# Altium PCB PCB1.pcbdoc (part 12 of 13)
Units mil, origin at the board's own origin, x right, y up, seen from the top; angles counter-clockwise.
Board outline 5895.51 x 5895.51 mil, 8 copper layers (Top Layer, L2_GND1, L3_SIG1, L4_GND2, L5_PWR, L6_SIG2, L7_GND3, Bottom Layer), stack 63.761 mil thick; 673 components, 558 nets, 2797 pads, 1861 vias.
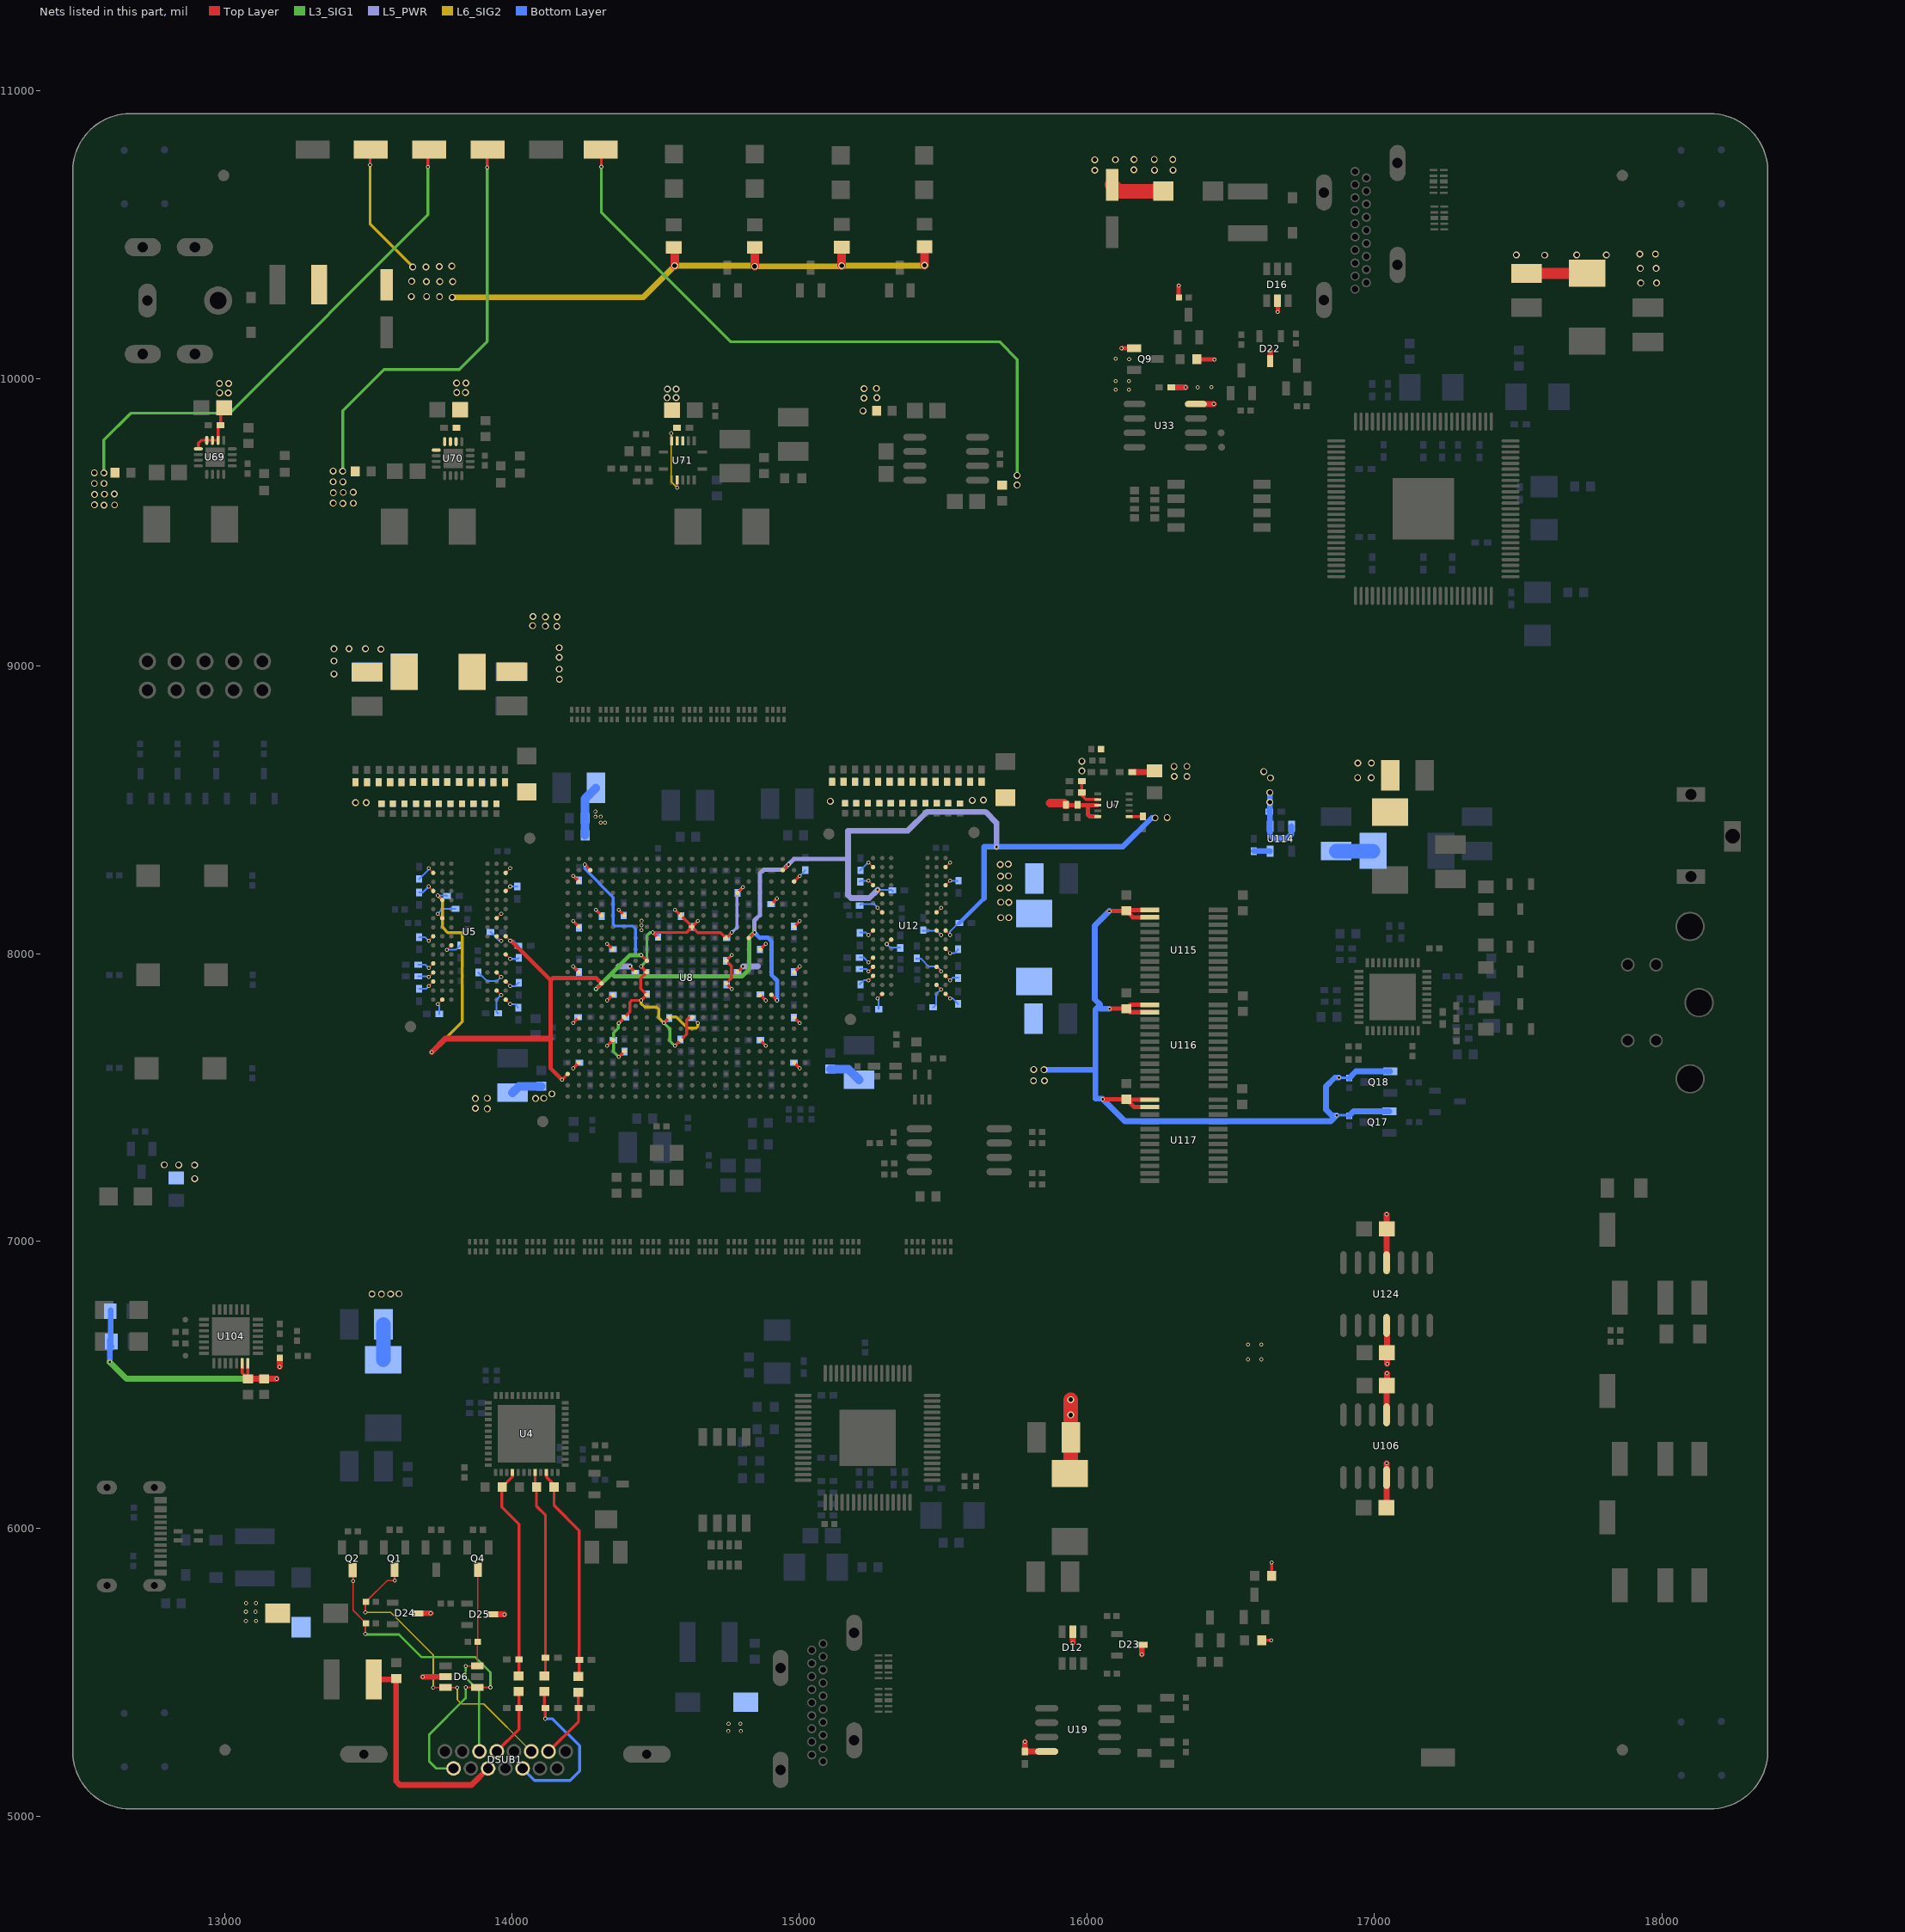
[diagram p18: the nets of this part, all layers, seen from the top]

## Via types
v1: diameter 23.62, hole 15.75, Top Layer to Bottom Layer, 621 vias
v2: diameter 13.8, hole 7.9, Top Layer to Bottom Layer, 567 vias
v3: diameter 13.78, hole 7.87, Top Layer to Bottom Layer, 529 vias
v4: diameter 13.78, hole 7.9, Top Layer to Bottom Layer, 114 vias
v5: diameter 15.75, hole 7.87, Top Layer to Bottom Layer, 16 vias
v6: diameter 24, hole 12, Top Layer to Bottom Layer, 10 vias
v7: diameter 11.81, hole 7.87, Top Layer to Bottom Layer, 4 vias

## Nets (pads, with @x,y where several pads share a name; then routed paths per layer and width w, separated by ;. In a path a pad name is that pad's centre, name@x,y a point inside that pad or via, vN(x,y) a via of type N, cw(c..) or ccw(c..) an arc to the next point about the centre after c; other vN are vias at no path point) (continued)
VCC_1V5: C42.2 C43.2 C44.2 C45.2 C46.2 C47.2 C48.2 C49.2 C50.2 C51.2 C52.2 C53.2 C66.2 C67.2 C68.2 C69.2 C70.2 C71.2 C72.2 C73.2 C74.2 C75.2 C76.2 C77.2 C120.2 C123.2 C311.2 C312.2 C345.1 C347.1 C349.1 L25.2 L34.1 Q17.1 Q18.1 R96.1 R180.2 R181.2 U7.2 U8.C2 U8.C21 U8.E19 U8.F4 U8.F6 U8.G2 U8.G21 U8.J5 U8.J18 U8.L2 U8.L7 U8.L16 U8.L21 U8.N5 U8.N18 U8.R2 U8.R21 U8.U5 U8.U18 U8.W2 U8.W21 U73.1 U115.1 U115.2 U116.1 U116.2 U117.1 U117.2 | length 6171.7
  Top Layer w10: v3(13914.39,10733.88) 13914.39,10800.96 U73.1@13915.39,10801.96 ; v2(14213.67,7601.05) U8.W2@14233.34,7620.73 ; v2(14213.67,7758.52) U8.R2@14233.34,7778.2 ; v2(14213.67,7955.37) U8.L2@14233.34,7935.7 ; v2(14213.67,8112.84) U8.G2@14233.34,8093.16 ; v2(14213.67,8270.32) U8.C2@14233.34,8250.65 ; v2(14292.41,8152.21) U8.F4@14312.08,8132.53 ; v2(14331.79,7679.79) U8.U5@14351.46,7699.47 ; v2(14331.79,7837.27) U8.N5@14351.46,7856.94 ; v2(14331.79,8034.1) U8.J5@14351.46,8014.43 ; v2(14371.15,8152.21) U8.F6@14390.82,8132.53 ; v2(14410.52,7955.37) U8.L7@14430.19,7935.7 ; U8.L16@14784.52,7935.7 v2(14804.2,7955.37) ; U8.U18@14863.26,7699.47 v2(14882.94,7679.79) ; U8.N18@14863.26,7856.94 v2(14882.94,7837.27) ; U8.J18@14863.26,8014.43 v2(14882.94,8034.1) ; U8.E19@14902.63,8171.9 v2(14922.31,8191.57) ; U8.W21@14981.36,7620.73 v2(15001.04,7601.05) ; U8.R21@14981.36,7778.2 v2(15001.04,7758.52) ; U8.L21@14981.36,7935.7 v2(15001.04,7955.37) ; U8.G21@14981.36,8093.16 v2(15001.04,8112.84) ; U8.C21@14981.36,8250.65 v2(15001.04,8270.32) ; C120.2@15981.86,8599.95 C123.2@15981.86,8559.95 15981.86,8550.5 15996.66,8535.7 U7.2@16037.24,8535.7
  Top Layer w15: v3(16055.36,7493.44) C347.1@16137.36,7493.44 C347.1@16139.06,7491.74 ; v3(16078.36,8148) 16078.8,8148.44 C345.1@16137.36,8148.44 ; v3(16079.36,7808) 16079.8,7808.44 C349.1@16137.36,7808.44 ; U117.2@16218.36,7466.15 16164.65,7466.15 C347.1@16139.06,7491.74 ; U117.1@16218.36,7491.74 C347.1@16139.06,7491.74 ; U116.2@16218.36,7796.15 16149.65,7796.15 C349.1@16137.36,7808.44 ; U116.1@16218.36,7821.74 16150.66,7821.74 C349.1@16137.36,7808.44 ; U115.2@16218.36,8126.15 16159.65,8126.15 C345.1@16137.36,8148.44 ; U115.1@16218.36,8151.74 16140.66,8151.74 C345.1@16137.36,8148.44
  L3_SIG1 w10: v1(13411.57,9677.79) 13411.57,9888.31 13554.67,10031.42 13816.93,10031.42 13914.43,10128.92 v3@13914.43,10733.84
  L5_PWR w20: 14370.36,7955.37 v2(14410.52,7955.37) ; v2(14804.2,7955.37) 14855.99,7955.37 14856.36,7955
  Bottom Layer w6: v2(14213.67,7601.05) 14233.49,7620.88 C52.2@14234.69,7620.88 ; v2(14213.67,7758.52) 14230.9,7775.75 C47.2@14230.9,7779 ; v2(14213.67,8112.84) 14233.36,8093.15 C51.2@14233.36,8089.54 ; v2(14213.67,8270.32) 14217.58,8270.32 C48.2@14233.36,8254.54 ; v2(14331.79,7679.79) 14334.61,7679.79 C44.2@14352.82,7698 ; v2(14331.79,7837.27) 14350.9,7856.38 C50.2@14350.9,7857 ; v2(14331.79,8034.1) 14332.8,8034.1 C45.2@14351.9,8015 ; v2(14371.15,8152.21) 14371.15,8150.75 C311.2@14389.36,8132.54 ; v2(14410.52,7955.37) 14428.81,7937.08 C49.2@14428.81,7932.42 ; C72.2@14784.9,7936 v2@14804.2,7955.3 ; C76.2@14862.36,8014.46 14863.3,8014.46 v2(14882.94,8034.1) ; C70.2@14863.82,7858 14882.94,7838.88 v2(14882.94,7837.27) ; C77.2@14864.82,7697 14865.73,7697 v2(14882.94,7679.79) ; C75.2@14901.9,8170 14922.31,8190.41 v2(14922.31,8191.57) ; C68.2@14979.36,7779.54 14980.02,7779.54 v2(15001.04,7758.52) ; C71.2@14980.9,7620 14982.09,7620 v2(15001.04,7601.05) ; C73.2@14981.36,8094.46 14982.66,8094.46 v2(15001.04,8112.84) ; C69.2@14982.36,7933.46 15001.04,7952.14 v2(15001.04,7955.37) ; v2(15001.04,8270.32) 15020.36,8289.64 C74.2@15020.36,8290.54
  Bottom Layer w10: v2(14213.67,7955.37) 14233.13,7935.91 C53.2@14233.25,7935.91 ; v2(14292.41,8152.21) 14312.36,8132.26 C46.2@14312.36,8130.54 ; v3(16868.82,7437.63) 16869.21,7438.02 R180.2@16914.09,7438.02 ; v3(16876.59,7568.85) 16877.46,7567.98 R181.2@16912.15,7567.98
  Bottom Layer w20: v1(15850.36,7596) 16027.61,7596 16029.36,7597.75 ; v3(16078.36,8148) 16027.36,8097 16027.36,7841 16046.36,7822 ; v3(16079.36,7808) 16046.36,7808 16046.36,7822 ; v3(16876.59,7568.85) 16862.21,7568.85 16831.36,7538 16831.36,7457 16850.73,7437.63 v3(16868.82,7437.63) 16848.19,7417 16131.8,7417 v3(16055.36,7493.44) 16052.8,7496 16029.36,7496 16029.36,7597.75 ; R180.2@16912.36,7436.04 16927.72,7451.4 Q17.1@17051.73,7451.4 ; R181.2@16912.36,7567.04 16935.72,7590.4 Q18.1@17054.73,7590.4 ; 16029.36,7597.75 16029.36,7805 16046.36,7822
  Bottom Layer w30: C42.2@14002.36,7516.26 14024.54,7538.44 C43.2@14102.36,7538.44 ; C67.2@15107.36,7598.44 15170.18,7598.44 C66.2@15207.36,7561.26
  other v1: 13914.36,7460 13873.36,7462 13873.36,7496 14082.36,7496 13914.36,7497 14111.36,7497 14139.36,7512 15814.36,7558 15852.36,7558 15815.36,7597 15982.36,8635 15982.36,8669 13378.63,9566.45 13412.15,9565.57 13448.58,9566.16 13378.92,9602.3 13413.31,9603.47 13448,9604.05 13378.34,9641.06 13412.15,9640.77 13378.34,9678.08
VCC_1V8: C337.2 C343.2 L42.1 U114.5 | length 184.9
  Bottom Layer w20: C343.2@16580.36,8356.54 16636.21,8356.54 U114.5@16636.82,8355.93
  Bottom Layer w50: C337.2@16867.36,8356.26 16994.51,8356.26 L42.1@16995.25,8357
VCC_3V3: C125.2 C150.2 C204.2 C208.2 C210.2 C211.2 C213.2 C215.2 C314.2 C315.2 C328.2 C344.2 L1.2 L23.2 L28.1 L29.1 L30.1 L31.1 L32.1 L39.1 Q9.1 R31.1 R164.2 R165.2 U19.8 U26.2 U27.2 U33.8 U72.1 U104.6 U104.7 U114.1 U114.3 | length 4143.4
  Top Layer w10: U104.6@13062.06,6575.31 13062.06,6542.1 C314.2@13081.75,6522.41 ; U104.7@13081.75,6575.31 C314.2@13081.75,6522.41 ; C314.2@13082.69,6521.47 C314.2@13081.75,6522.41 ; U72.1@13706.82,10808.85 13708.31,10807.35 v3(13708.31,10735.63) ; U26.2@16607.64,5611.71 v3(16641.36,5611.71) ; v3(16642.36,5883) 16642.64,5882.71 U27.2@16642.64,5836.71
  Top Layer w15: v3(16120.2,10105.05) Q9.1@16163.22,10105.05
  Top Layer w20: C314.2@13082.69,6521.47 13138.26,6521.47 C315.2@13138.36,6521.56 v3(13181.36,6521.56) ; v3(13192.36,6563) 13192.69,6563.33 R31.1@13192.69,6593.52 ; C150.2@15784.31,5221.87 C150.2@15787.85,5225.41 ; v3(15784.36,5259) 15784.36,5228.9 C150.2@15787.85,5225.41 ; U19.8@15860.16,5225.41 C150.2@15787.85,5225.41 ; C125.2@16156.82,8631 16231.32,8631 L1.2@16235.36,8635.04 ; C210.2@16293.82,9969 v3(16343.36,9969) ; U33.8@16378.86,9911 v3(16441.36,9911)
  Top Layer w40: C213.2@17528.83,10365.31 17739.56,10365.31 L31.1@17739.86,10365.61
  Top Layer w50: L30.1@15940.93,6191.88 15943.68,6194.62 C211.2@15943.68,6317.79 v1(15943.68,6395.66) 15943.68,6448.68 v1(15943.36,6449)
  L3_SIG1 w10: v1(12580.87,9671.84) 12580.87,9786.14 12674.08,9879.35 13018.85,9879.35 13708.31,10568.81 v3(13708.31,10735.63)
  L3_SIG1 w20: v3(12601.03,6580.15) 12659.62,6521.56 v3(13181.36,6521.56)
  Bottom Layer w20: v3(12601.03,6580.15) 12601.6,6580.72 R164.2@12601.6,6656.88 ; R165.2@12604.86,6759.82 12604.86,6635.81 R164.2@12606.91,6633.76 ; v1(16636.36,8560) v1(16636.36,8526.11) 16636.36,8496.46 C344.2@16633.9,8494 16636.83,8491.07 U114.1@16636.83,8442.55 16636.83,8412.53 16648.36,8401 16697.36,8401 16711.62,8415.26 U114.3@16711.62,8442.55
  Bottom Layer w50: L32.1@13552.55,6587.3 13553.1,6587.84 C215.2@13553.1,6711
  other v1: 13513.39,6815.89 13546.42,6815.6 13578.08,6816.06 13607.46,6816.97 16638.36,8611 16941.61,8612.22 16989.1,8611.89 16303.82,8616.44 16347.87,8616.44 16615.36,8633 16303.15,8650.97 16347.87,8651.19 16941.94,8662.7 16989.43,8662.7 13381.55,8972.51 13381.25,9017.58 13544.76,9058.99 13381.25,9059.6 13433.31,9059.9 13490.86,9059.9 12547.93,9560.5 12581.45,9559.62 12617.89,9560.21 12548.23,9596.35 12582.62,9597.51 12617.3,9598.1 12547.64,9635.11 12581.45,9634.82 12547.64,9672.13 17926.44,10331.81 17980.99,10331.81 17924.95,10382.61 17979.49,10382.61 17592.04,10428.77 17493.42,10429.77 17703.62,10429.77 17806.73,10429.77 17922.96,10432.42 17977.5,10432.42
  other v3: 16100.36,9961 16146.36,9961 16385.36,9969 16433.36,9970 16100.36,9991 16146.36,9991 16146.83,10067.36 16100.36,10069
VCC_5V: C153.1 C192.1 C193.2 C196.2 C199.2 C217.1 C218.1 C219.1 C354.2 C356.2 D5.2 D6.5 D11.2 D12.5 D16.5 D17.1 D22.3 D23.3 D24.3 D25.3 D29.1 F2.1 L44.1 R112.2 R143.2 R144.2 R145.2 R147.2 R148.2 U11.1 U31.2 U69.10 U69.11 U69.12 U69.13 U70.10 U70.11 U70.12 U70.13 U71.4 U71.5 U71.6 U71.10 U106.4 U124.4 | length 3801.1
  Top Layer w5: v3(14574.64,9620.19) 14574.79,9620.35 U71.10@14574.79,9650.03
  Top Layer w10: U69.13@12909.23,9755.26 12909.23,9774.88 12919.36,9785 12977.91,9785 U69.10@12978.12,9784.78 12978.12,9829.31 C217.1@12986.82,9838 12986.82,9886.09 C193.2@12998.73,9898 ; v3(13506.83,10742.48) 13506.83,10796.91 U11.1@13516.66,10806.75
  Top Layer w15: R112.2@16319.12,10280.07 16319.12,10322.35 v3(16319.57,10322.8) ; U31.2@16380.2,10066.16 16443.07,10066.16 v3(16443.29,10065.94) ; v3(16663.44,10231.78) 16663.67,10232 D16.5@16663.67,10271.85
  Top Layer w20: D24.3@13669.67,5705.83 v3(13717.47,5705.83) ; v3(13690.13,5485.15) 13690.42,5484.86 D6.5@13768.82,5484.86 ; D25.3@13932.29,5702.36 13973.09,5702.36 v3(13973.48,5701.98) ; v3(15950.92,5603) D12.5@15950.92,5641.45 ; v3(16190.67,5563) D23.3@16190.67,5596.33 ; v3(16637.42,10095.3) 16638.09,10094.64 D22.3@16638.09,10059.1 ; U106.4@17042.36,6396.02 17042.36,6496.63 C354.2@17043.73,6498 17043.73,6540.23 v3(17043.57,6540.4) ; U124.4@17042.36,6925.02 C356.2@17042.36,7042.63 ; v3(17042.4,7093.84) C356.2@17042.36,7042.63 ; C356.2@17042.73,7043 C356.2@17042.36,7042.63
  Top Layer w30: R143.2@14563.18,10455.6 14566.36,10452.42 v1(14566.36,10392) ; v1(14844.36,10390) R144.2@14844.36,10455.6 ; v1(15147.36,10392) R145.2@15147.36,10456.63 ; v1(15435.36,10394) R147.2@15435.36,10457.63
  Top Layer w50: C153.1@16087.36,10673.68 16110.04,10651 D17.1@16266.04,10651
  L6_SIG2 w5: v3(14554.1,9809.28) 14554.1,9640.74 v3(14574.64,9620.19)
  L6_SIG2 w10: v3(13506.83,10742.48) 13506.83,10536.53 v1(13655.36,10388)
  L6_SIG2 w20: v1(13792.36,10282) 14456.36,10282 v1(14566.36,10392) 14842.36,10392 v1(14844.36,10390) 15145.36,10390 v1(15147.36,10392) 15433.36,10392 v1(15435.36,10394)
  other v1: 12896.5,7217.37 12791.18,7265.3 12840.93,7265.18 12896.37,7264.79 15221.06,9887.45 15224.77,9931.95 14539.88,9932.69 14571.17,9933.39 15269.27,9933.11 12983.1,9950.17 13013.12,9949.88 13808.16,9951.15 13838.18,9950.86 14540.94,9962.92 14571.17,9962.92 15225,9964.86 15267.88,9965.32 12982.81,9982.81 13015.16,9982.81 13807.87,9983.79 13840.22,9983.79 13748.36,10284 13650.36,10285 13703.36,10285 13702.36,10337 13749.36,10337 13794.36,10337 13651.36,10338 13701.36,10388 13747.36,10389 13791.36,10391 16027.49,10724.21 16299.68,10724.46 16163.61,10725.29 16235.01,10724.63 16027.46,10760.49 16099.19,10760.82 16163.94,10761.16 16298.68,10761.32 16234.34,10761.82
  other v4: 14752.7,5295.96 14796.27,5295.96 14753.73,5321.58 14795.24,5321.58 13074.63,5679.2 13109.71,5678.97 13074.63,5711.32 13108.8,5711.54 13075.09,5741.16 13109.49,5741.38
VCC_AUX: C17.2 C18.2 C19.2 C20.2 C21.2 C22.2 C23.2 C24.2 C25.2 C29.2 C205.2 C303.2 C304.2 C305.2 C306.2 C307.2 C308.2 C309.2 L28.2 U8.D16 U8.F11 U8.G12 U8.H9 U8.H15 U8.K15 U8.L8 U8.M15 U8.N8 U8.R6 U8.R10 U8.R12 U8.U11 U8.V6 | length 2504.9
  Top Layer w10: v2(14371.15,7640.42) U8.V6@14390.82,7660.1 ; v2(14371.15,7758.52) U8.R6@14390.82,7778.2 14410.36,7797.73 14410.36,7831 14416.63,7837.27 v2(14449.89,7837.27) U8.N8@14469.56,7856.94 14448.36,7878.15 14448.36,7914.49 U8.L8@14469.56,7935.7 v2(14449.89,7955.37) ; U8.H9@14508.93,8053.8 v2(14489.26,8073.47) 14607.37,8073.47 U8.G12@14627.06,8093.16 ; v2(14528.63,7758.52) U8.R10@14548.3,7778.2 ; v2(14567.99,7679.79) U8.U11@14587.66,7699.47 14608.36,7720.16 14608.36,7769 14617.55,7778.2 U8.R12@14627.06,7778.2 ; v2(14567.99,8152.21) U8.F11@14587.66,8132.53 U8.G12@14627.03,8093.16 ; v2(14646.74,8112.84) U8.G12@14627.06,8093.16 ; v2(14764.84,7876.62) U8.M15@14745.16,7896.3 14763.36,7914.49 14763.36,7956.86 U8.K15@14745.16,7975.06 v2(14764.84,7994.73) ; v2(14764.84,8073.47) U8.H15@14745.16,8053.8 14725.96,8073 14647.23,8073 U8.G12@14627.06,8093.16 ; U8.D16@14784.52,8211.27 v2(14804.2,8230.95)
  L3_SIG1 w10: v2(14371.15,7640.42) 14353.36,7658.21 14353.36,7724 14370.36,7741 14370.36,7757.73 v2(14371.15,7758.52) ; v2(14449.89,7955.37) 14469.36,7974.84 14469.36,8062 14480.83,8073.47 v2(14489.26,8073.47) ; v2(14528.63,7758.52) 14549.36,7737.79 14549.36,7696 14565.57,7679.79 v2(14567.99,7679.79)
  L5_PWR w10: v2(14764.84,8073.47) 14779.37,8088 14782.36,8088 14782.36,8209.11 v2(14804.2,8230.95)
  L6_SIG2 w10: v2(14449.89,7837.27) 14449.89,7826.47 14462.36,7814 14503.36,7814 14510.36,7807 14510.36,7776.79 v2(14528.63,7758.52) 14550.11,7780 14571.36,7780 14610.36,7741 14641.36,7741 14646.74,7746.38 v2(14646.74,7758.52)
  Bottom Layer w6: v2(14371.15,7640.42) 14372.24,7640.42 C309.2@14391.36,7659.54 ; v2(14371.15,7758.52) 14375.34,7758.52 C22.2@14394.82,7778 ; v2(14449.89,7837.27) 14469.28,7856.67 C306.2@14469.28,7858.91 ; v2(14449.89,7955.37) 14467.36,7937.9 C305.2@14467.36,7934.54 ; v2(14528.63,7758.52) 14529.96,7758.52 C304.2@14547.73,7776.29 ; v2(14567.99,7679.79) 14586.36,7698.16 C25.2@14586.36,7701.46 ; v2(14567.99,8152.21) 14588.36,8131.84 C21.2@14588.36,8130.54 ; C20.2@14625.36,8093.54 14644.66,8112.84 v2(14646.74,8112.84) ; C19.2@14625.9,7776 14629.26,7776 v2(14646.74,7758.52) ; C307.2@14746.82,8054 14764.84,8072.02 v2(14764.84,8073.47) ; C24.2@14785.36,8210.54 14804.2,8229.38 v2(14804.2,8230.95)
  Bottom Layer w10: v2(14489.26,8073.47) 14497.43,8073.47 C303.2@14509.36,8061.54 ; C23.2@14743.02,7973.84 14743.94,7973.84 v2(14764.84,7994.73) ; C308.2@14746.91,7892.07 14749.39,7892.07 v2(14764.84,7876.62)
  Bottom Layer w30: C18.2@14254.92,8411 C29.2@14254.92,8471 14254.92,8538.82 C17.2@14292.1,8576
  other v1: 14165.36,8954 14164.36,8989 14164.36,9030 14164.36,9064
  other v4: 14451.36,8082 14451.36,8098 14451.36,8114 14308.54,8455.53 14324.17,8455.53 14290.36,8475.78 14308.54,8475.78 14290.36,8494
VDD_DDR3: C261.2 C262.2 C263.2 C264.2 C265.2 C266.2 C267.2 C268.2 C269.2 C270.2 C271.2 C272.2 C273.2 C274.2 C275.2 C276.2 C277.2 C278.2 C279.2 C280.2 C281.2 C282.2 C283.2 C284.2 C285.2 C286.2 C287.2 C288.2 C289.2 C290.2 C291.2 C292.2 C313.2 L34.2 U5.A1 U5.A8 U5.B2 U5.C1 U5.C9 U5.D2 U5.D9 U5.E9 U5.F1 U5.G7 U5.H2 U5.H9 U5.K2 U5.K8 U5.N1 U5.N9 U5.R1 U5.R9 U12.A1 U12.A8 U12.B2 U12.C1 U12.C9 U12.D2 U12.D9 U12.E9 U12.F1 U12.G7 U12.H2 U12.H9 U12.K2 U12.K8 U12.N1 U12.N9 U12.R1 U12.R9 | length 2304
  Top Layer w4.7: v2(13710.63,7887.02) U5.C9@13726.38,7902.77 ; v2(13710.63,7918.52) U5.D9@13726.38,7934.27 ; v2(13710.63,7950.02) U5.E9@13726.38,7965.76 ; v2(13710.63,8044.51) U5.H9@13726.38,8060.25 ; v2(13710.63,8233.48) U5.N9@13726.38,8217.73 ; v2(13710.63,8296.47) U5.R9@13726.38,8280.72 ; v2(13742.12,7824.03) U5.A8@13757.87,7839.78 ; v2(13742.12,8138.98) U5.K8@13757.87,8123.24 ; v2(13773.62,8013.02) U5.G7@13789.37,8028.76 ; U5.B2@13946.85,7871.28 v2(13962.59,7855.53) ; U5.D2@13946.85,7934.27 v2(13962.59,7918.52) ; U5.H2@13946.85,8060.25 v2(13962.59,8044.51) ; U5.K2@13946.85,8123.24 v2(13962.59,8138.98) ; U5.A1@13978.34,7839.78 v2(13994.08,7824.03) ; U5.C1@13978.34,7902.77 v2(13994.08,7887.02) ; U5.F1@13978.34,7997.26 v2(13994.08,7981.52) ; U5.N1@13978.34,8217.73 v2(13994.08,8233.48) ; U5.R1@13978.34,8280.72 v2(13994.08,8296.47) ; v2(15240.63,7907.02) U12.C9@15256.38,7922.77 ; v2(15240.63,7938.52) U12.D9@15256.38,7954.27 ; v2(15240.63,7970.02) U12.E9@15256.38,7985.76 ; v2(15240.63,8064.51) U12.H9@15256.38,8080.25 ; v2(15240.63,8253.48) U12.N9@15256.38,8237.73 ; v2(15240.63,8316.47) U12.R9@15256.38,8300.72 ; v2(15272.12,7844.03) U12.A8@15287.87,7859.78 ; v2(15272.12,8158.98) U12.K8@15287.87,8143.24 ; v2(15303.62,8033.02) U12.G7@15319.37,8048.76 ; U12.B2@15476.85,7891.28 v2(15492.59,7875.53) ; U12.D2@15476.85,7954.27 v2(15492.59,7938.52) ; U12.H2@15476.85,8080.25 v2(15492.59,8064.51) ; U12.K2@15476.85,8143.24 v2(15492.59,8158.98) ; U12.A1@15508.34,7859.78 v2(15524.08,7844.03) ; U12.C1@15508.34,7922.77 v2(15524.08,7907.02) ; U12.F1@15508.34,8017.26 v2(15524.08,8001.52) ; U12.N1@15508.34,8237.73 v2(15524.08,8253.48) ; U12.R1@15508.34,8300.72 v2(15524.08,8316.47)
  Bottom Layer w6: C275.2@13673.82,7921 13708.16,7921 v2(13710.63,7918.52) ; C265.2@13673.82,7961 13699.65,7961 v2(13710.63,7950.02) ; C274.2@13677.36,7877.46 13701.07,7877.46 v2(13710.63,7887.02) ; C266.2@13677.36,8057.46 13697.68,8057.46 v2(13710.63,8044.51) ; C267.2@13677.36,8212.46 13689.62,8212.46 v2(13710.63,8233.48) ; C268.2@13677.36,8259.54 13710.63,8292.82 v2(13710.63,8296.47) ; v2(13742.12,7824.03) 13746.82,7819.34 C273.2@13746.82,7790 ; v2(13742.12,8138.98) 13759.3,8156.16 C276.2@13804.64,8156.16 ; v2(13773.62,8013.02) 13805.2,8013.02 C269.2@13820.98,8028.8 ; C272.2@13883.14,7934.47 13912.61,7905 13949.07,7905 v2(13962.59,7918.52) ; C264.2@13926.05,8075.32 13956.86,8044.51 v2(13962.59,8044.51) ; C263.2@13952.26,7792.35 13946.36,7798.25 13946.36,7840 13961.89,7855.53 v2(13962.59,7855.53) ; v2(13994.08,7824.03) 14010.78,7824.03 C271.2@14022.36,7812.46 ; v2(13994.08,7887.02) 14011.77,7887.02 C262.2@14023.62,7898.87 ; v2(13994.08,7981.52) 14020.17,7981.52 C270.2@14024.57,7985.92 ; v2(13994.08,8233.48) C261.2@14019.36,8233.46 ; C279.2@15209.43,7986.82 15223.83,7986.82 v2(15240.63,7970.02) ; C288.2@15209.57,7892.73 15223.86,7907.02 v2(15240.63,7907.02) ; C277.2@15210.3,8250.64 15213.13,8253.48 v2(15240.63,8253.48) ; C281.2@15210.46,8168.55 15214.26,8172.35 15258.91,8172.35 15272.12,8159.13 v2(15272.12,8158.98) ; C285.2@15211.14,8289.4 15238.21,8316.47 v2(15240.63,8316.47) ; C278.2@15211.36,8073.29 15231.85,8073.29 v2(15240.63,8064.51) ; C287.2@15211.67,7945.95 15233.2,7945.95 v2(15240.63,7938.52) ; v2(15272.12,7844.03) 15274.87,7841.29 C280.2@15274.87,7806.65 ; v2(15303.62,8033.02) 15316.01,8020.63 C286.2@15350.24,8020.63 ; C283.2@15405.69,7981.68 15423.6,7981.68 15450.14,7955.13 15478.57,7955.13 15492.59,7941.12 v2(15492.59,7938.52) ; C282.2@15428.34,8079.99 15477.1,8079.99 v2(15492.59,8064.51) ; C289.2@15465.82,7813 15475.36,7822.54 15475.36,7858.3 v2(15492.59,7875.53) ; v2(15524.08,7844.03) 15532.59,7844.03 C290.2@15551.25,7825.38 ; v2(15524.08,7907.02) 15533.22,7916.17 C291.2@15552.72,7916.17 ; v2(15524.08,8001.52) 15539.28,8001.52 C292.2@15552.51,8014.75 ; v2(15524.08,8253.48) 15549.54,8253.48 C284.2@15550.93,8252.09
  other v1: 15700.36,8125 15728.36,8125 15728.36,8178 15700.36,8179 15698.36,8228 15728.36,8229 15699.36,8269 15727.36,8270 15698.36,8310 15726.36,8311 14156.36,9138 14116.36,9139 14072.36,9140 14116.36,9171 14157.36,9171 14073.36,9172
VDD_DDR3_REF: C102.1 C103.1 C104.1 C105.1 C124.1 U5.H1 U5.M8 U7.6 U8.B3 U8.B20 U8.H17 U8.K8 U8.M4 U8.N19 U8.Y1 U12.H1 U12.M8 | length 6372
  Top Layer w4.7: v2(13742.12,8201.99) U5.M8@13757.87,8186.24 ; U5.H1@13978.34,8060.25 v2(13994.08,8044.51) ; v2(15272.12,8221.99) U12.M8@15287.87,8206.24 ; U12.H1@15508.34,8080.25 v2(15524.08,8064.51)
  Top Layer w10: v2(14174.29,7561.68) U8.Y1@14193.96,7581.35 ; v2(14253.04,8309.69) U8.B3@14272.71,8290.01 ; v2(14292.41,7876.62) U8.M4@14312.08,7896.3 ; v2(14449.89,7994.73) U8.K8@14469.56,7975.06 ; U8.H17@14823.89,8053.8 v2(14843.57,8073.47) ; U8.N19@14902.63,7856.94 v2(14922.31,7837.27) ; U8.B20@14942,8290.01 v2(14961.68,8309.69) ; U7.6@16147.47,8476.6 16193.5,8476.6 C124.1@16194.36,8477.46
  Top Layer w15: v2(13994.08,8044.51) 13997.85,8044.51 14135.36,7907 ; v2(14174.29,7561.68) 14135.36,7600.61 14135.36,7703.68 14135.36,7907 ; U8.M4@14312.08,7896.3 14292.81,7915.57 14143.93,7915.57 14135.36,7907
  Top Layer w20: v3(13721.36,7657) 13768.36,7704 14135.03,7704 14135.36,7703.68
  L3_SIG1 w15: v2(14292.41,7876.62) 14346.74,7930.95 ; v2(14449.89,7994.73) 14410.52,7994.73 14346.74,7930.95 ; v2(14843.57,8073.47) 14825.36,8055.26 14825.36,7946 14800.36,7921 14356.69,7921 14346.74,7930.95
  L5_PWR w15: v2(14843.57,8073.47) 14843.57,8115.21 14862.15,8133.79 14862.15,8277.09 14876.15,8291.09 14943.08,8291.09 v2(14961.68,8309.69) 14981.13,8329.15 15169.36,8329.15
  L5_PWR w20: v2(15272.12,8221.99) 15243.14,8193 15179.36,8193 15169.36,8203 15169.36,8329.15 15169.36,8427.25 15377.57,8427.25 15443.44,8493.11 15647.25,8493.11 15685.36,8455 v4(15685.36,8371)
  L6_SIG2 w10: v3(13721.36,7657) 13827.36,7763 13827.36,8073 13777.36,8073 13758.22,8092.14 13758.22,8186 13758.11,8186 v2(13742.12,8201.99)
  Bottom Layer w6: v2(13742.12,8201.99) 13772.09,8201.99 C102.1@13774.04,8200.03 ; v2(13994.08,8044.51) 14005.48,8044.51 C103.1@14022.42,8027.56 ; v2(15272.12,8221.99) 15319.81,8221.99 C104.1@15326.8,8214.99 ; v2(15524.08,8064.51) 15524.08,8076.84 C105.1@15554.09,8106.85
  Bottom Layer w10: v2(14253.04,8309.69) 14253.04,8295.32 14352.36,8196 14352.36,8102 14358.36,8096 14420.16,8096 14430.16,8086 14430.16,8001.45 14436.88,7994.73 v2(14449.89,7994.73)
  Bottom Layer w15: v2(14843.57,8073.47) 14862.04,8055 14891.36,8055 14902.53,8043.83 14902.53,7925.83 14922.31,7906.05 v2(14922.31,7837.27) ; C105.1@15555.9,8106 15642.36,8192.46
  Bottom Layer w20: 15642.36,8192.46 15642.36,8372 16125.36,8372 16225.36,8472 v1(16237.36,8472)
  other v1: 16279.36,8473
VEE_N5V: C355.2 C357.2 L45.2 U106.11 U124.11 U126.1 | length 2581.8
  Top Layer w10: U126.1@14309.08,10806.94 14311.07,10804.95 v3(14311.07,10735.88)
  Top Layer w20: C355.2@17041.73,6073 17042.36,6073.63 U106.11@17042.36,6177.98 v3(17042.36,6228) ; U124.11@17042.36,6706.98 17043.73,6705.61 C357.2@17043.73,6612 17043.73,6573.63 v3(17044.36,6573)
  L3_SIG1 w10: v3(14311.07,10735.88) 14311.27,10735.68 14311.27,10576.45 14760.13,10127.59 15695.68,10127.59 15757.31,10065.95 v1(15757.31,9663.11)
  other v1: 15757.12,9629.3
  other v3: 16560.36,6589 16606.36,6589 16606.36,6640 16560.36,6641
VGA_5V: C118.2 DSUB1.9 U18.2 | length 789.7
  Top Layer w20: U18.2@13519.33,5476 13594.92,5476 C118.2@13598.36,5479.44 C118.2@13602.36,5483.44 ; C118.2@13597.36,5476.44 13597.36,5122 13610.36,5109 13859.82,5109 DSUB1.9@13917.3,5166.47
VGA_B: C114.2 R84.2 U4.28 U17.1 | length 748.1
  Top Layer w10: U4.28@14002.15,6196.14 14002.15,6181.13 R84.2@13966.02,6145 13965.36,6144.34 13965.36,6075 14024.82,6015.54 C114.2@14024.82,5546 14024.82,5490.02 U17.1@14023.36,5488.56
VGA_G: C113.2 R85.2 U4.32 U16.1 | length 724.5
  Top Layer w10: U4.32@14080.89,6196.14 14080.89,6150.13 R85.2@14086.02,6145 14085.36,6144.34 14085.36,6079 14116.9,6047.46 C113.2@14116.9,5551 14116.9,5492.1 U16.1@14113.36,5488.56
VGA_R: C112.2 R86.2 U4.34 U15.1 | length 758.6
  Top Layer w10: U4.34@14120.26,6196.14 14120.26,6179.33 14146.7,6152.89 R86.2@14146.7,6145 14146.7,6080.66 14234.21,5993.14 C112.2@14234.21,5543.68 14234.21,5489.78 U15.1@14230.67,5486.24
VGA_SCL: D6.1 DSUB1.15 Q2.3 R91.1 | length 1276.2
  Top Layer w4.7: Q2.3@13446.36,5855.98 13447.36,5854.98 v3(13447.36,5818) 13447.36,5716.35 R91.1@13492.48,5671.23 13490.36,5669.1 v3(13490.36,5634) ; v3(13839.35,5448.37) 13839.53,5448.19 D6.1@13879.85,5448.19 v3(13925.36,5448.19)
  L3_SIG1 w7.9: v3(13490.36,5634) 13492.36,5632 13607.36,5632 13685.36,5554 13871.36,5554 13925.36,5500 v3(13925.36,5448.19) ; DSUB1.15@13797.22,5166.47 13736.88,5166.47 13712.36,5191 13712.36,5284 13839.36,5411 v3(13839.35,5448.37)
  Bottom Layer w4.7: v3(13925.36,5448.19) v3@13925.36,5449
VGA_SDA: D6.6 DSUB1.12 Q1.3 R90.2 | length 1074.6
  Top Layer w4.7: v3(13490.36,5709) 13490.36,5744.1 R90.2@13492.48,5746.23 13566.25,5820 v3(13592.36,5820) 13592.05,5820.31 Q1.3@13592.05,5856.67 ; v3(13726.36,5447) 13726.62,5447.26 D6.6@13770.54,5447.26 ; D6.6@13769.61,5448.19 D6.6@13770.54,5447.26 ; v3(13809.47,5447.26) D6.6@13770.54,5447.26
  L6_SIG2 w5: v3(13490.36,5709) 13578.36,5709 13726.36,5561 v3(13726.36,5447) ; v3(13809.47,5447.26) 13810.36,5446.37 13810.36,5406 13825.36,5391 13901.94,5391 DSUB1.12@14067.41,5225.53
VGAC_B: C115.2 DSUB1.3 U17.2 | length 240.6
  Top Layer w10: DSUB1.3@13947.33,5225.53 14024.82,5303.01 C115.2@14024.82,5376 14024.82,5431.98 U17.2@14023.36,5433.44
VGAC_G: C116.2 DSUB1.2 U16.2 | length 570.5
  Top Layer w10: U16.2@14113.36,5433.44 14113.36,5379.54 C116.2@14116.9,5376 14116.36,5375.46 v3(14116.36,5339)
  Bottom Layer w10: DSUB1.2@14037.37,5166.47 14078.85,5125 14203.36,5125 14235.36,5157 14235.36,5245 14141.36,5339 v3(14116.36,5339)
VGAC_R: C117.2 DSUB1.1 U15.2 | length 249.4
  Top Layer w10: DSUB1.1@14127.45,5225.53 14231.9,5329.97 C117.2@14231.9,5376 14230.67,5377.22 U15.2@14230.67,5431.13
VSYC: D6.3 DSUB1.14 Q4.3 R95.1 | length 692.2
  Top Layer w4.7: v3(13839.13,5522.09) 13878.95,5522.09 D6.3@13879.85,5522.99 13879.85,5605.6 R95.1@13881.42,5607.17 13881.42,5856.04 Q4.3@13882.05,5856.67
  L3_SIG1 w7.9: v3(13839.13,5522.09) 13839.13,5483.22 13885.36,5437 13885.36,5227.47 DSUB1.14@13887.29,5225.53
VTT_DDR3: C78.2 C79.2 C80.2 C81.2 C82.2 C83.2 C84.2 C85.2 C86.2 C87.2 C88.2 C89.2 C90.2 C91.2 C92.2 C93.2 C94.2 C95.2 C96.2 C97.2 C98.2 C99.2 C100.2 C101.2 C121.2 C122.2 C220.2 C221.2 C222.2 C223.2 C224.2 C225.2 C226.2 C227.2 C228.2 C229.2 C230.2 C231.2 C232.2 C233.2 C234.2 C235.2 C236.2 C237.2 C238.2 C239.2 C240.2 C241.2 C242.2 C243.2 C244.2 C245.2 C246.2 C247.2 C248.2 C249.2 C250.2 C251.2 C259.1 C260.1 R27.2 R29.2 R30.2 R32.2 R33.2 R34.2 R35.2 R36.2 R37.2 R38.2 R39.2 R40.2 R41.2 R42.2 R43.2 R44.2 R45.2 R46.2 R47.2 R48.2 R49.2 R50.2 R54.2 R56.2 R57.2 R59.2 R60.2 R61.2 R62.2 R63.2 R64.2 R65.2 R66.2 R67.2 R68.2 R69.2 R70.2 R71.2 R72.2 R73.2 R74.2 R75.2 R76.2 R77.2 U7.3 U7.5 | length 237.3
  Top Layer w15: C122.2@15927.36,8517.46 15928.82,8516 U7.3@16037.24,8516 ; 16003.36,8515.99 16003.36,8483 16009.76,8476.6 U7.5@16037.24,8476.6
  Top Layer w30: 15872.36,8523 15921.82,8523 C122.2@15927.36,8517.46
  other v1: 13456.36,8525 13493.36,8525 15107.36,8530 15601.36,8533 15640.36,8534
pads on no net: CN2.7 CN2.8 D12.3 D16.3 DSUB1.4 DSUB1.11 R78.1 RN13.1 RN13.8 RN21.1 RN21.8 RN22.1 RN22.2 RN22.7 RN22.8 U2.2 U2.7 U2.49 U2.50 U2.51 U2.52 U2.53 U2.54 U2.55 U2.56 U2.59 U2.60 U2.61 U2.62 U2.63 U2.64 U2.65 U2.66 U2.69 U2.70 U2.71 U2.72 U2.73 U2.74 U2.75 U2.77 U2.96 U3.49 U5.J1 U5.J9 U5.L1 U5.L9 U5.M7 U7.9 U8.A2 U8.A4 U8.AA14 U8.AB9 U8.B1 U8.B2 U8.C4 U8.D3 U8.D5 U8.D12 U8.D13 U8.D14 U8.E4 U8.E5 U8.E6 U8.E8 U8.E10 U8.E12 U8.E14 U8.F7 U8.F8 U8.F9 U8.F10 U8.F12 U8.F13 U8.F14 U8.F15 U8.G7 U8.G8 U8.G9 U8.G11 U8.G13 U8.G16 U8.G17 U8.H8 U8.H10 U8.H11 U8.H12 U8.H13 U8.H14 U8.H16 U8.J7 U8.J16 U8.K7 U8.K16 U8.K18 U8.L4 U8.L6 U8.L15 U8.L17 U8.L19 U8.M3 U8.M5 U8.M6 U8.M7 U8.M8 U8.M19 U8.M20 U8.N4 U8.N6 U8.N7 U8.P3 U8.P4 U8.P5 U8.P6 U8.P7 U8.P8 U8.P15 U8.P16 U8.R4 U8.R16 U8.R17 U8.T3 U8.T4 U8.T17 U8.T18 U8.U4 U8.U16 U8.U17 U8.V3 U8.V15 U8.V19 U8.W1 U8.W3 U8.W12 U8.W13 U8.W17 U8.Y2 U8.Y7 U8.Y9 U8.Y13 U8.Y15 U8.Y18 U8.Y19 U8.Y20 U12.J1 U12.J9 U12.L1 U12.L9 U12.M7 U13.3 U86.1 U87.1 U88.1 U89.1 U90.1 U91.1 U92.1 U93.1 U94.1 U95.1 U96.1 U97.1 U98.1 U99.1 U100.1 U104.1 U104.2 U104.10 U104.12 U104.13 U104.14 U104.15 U104.16 U104.17 U104.18 U104.19 U104.20 U104.21 U104.22 U104.23 U104.24 U104.27 U104.28 U114.4 U116.9 U116.10 U116.14 U116.15 U117.3 U117.4 U117.20 U117.21 USB2.13 USB2.14 USB3.13 USB3.14 USB4.3 USB4.9
copper on no net: | length 3784.6
  Top Layer w7.9: v2(14253.04,7876.62) 14272.71,7896.3 ; v2(14292.41,7955.37) 14312.08,7935.7 ; 14784.52,8093.16 v3(14804.36,8113) ; 14902.63,7935.7 v2(14922.31,7955.37) ; 14942,7896.3 v2(14961.68,7876.62)
  Top Layer w10: v2(14174.29,7601.05) 14193.96,7620.73 ; v2(14253.04,7601.05) 14272.71,7620.73 ; v2(14253.04,7640.42) 14272.71,7660.1 ; v2(14253.04,7719.16) 14272.71,7738.84 ; v2(14292.41,7679.79) 14312.08,7699.47 ; v2(14292.41,7719.16) 14312.08,7738.84 ; v2(14292.41,7758.52) 14312.08,7778.2 ; v2(14489.26,7561.68) 14508.93,7581.35 ; 14784.52,7699.47 v2(14804.2,7679.79) ; 14784.52,7975.06 v2(14804.2,7994.73) ; 14784.52,8014.43 v2(14804.2,8034.1) ; 14823.89,7699.47 v2(14843.57,7679.79) ; 14823.89,7738.84 v2(14843.57,7719.16) ; 14863.26,7581.35 v2(14882.94,7561.68) ; 14902.63,7581.35 v2(14922.31,7561.68) ; 14902.63,7660.1 v2(14922.31,7640.42) ; 18200.36,10419 18300.36,10419 18300.36,10519 18200.36,10519 18200.36,10419
  L2_GND1 w10: 18200.36,10309 18300.36,10309 18300.36,10409 18200.36,10409 18200.36,10309
  L3_SIG1 w10: 18200.36,10199 18300.36,10199 18300.36,10299 18200.36,10299 18200.36,10199
  L4_GND2 w10: 18200.36,10089 18300.36,10089 18300.36,10189 18200.36,10189 18200.36,10089
  L5_PWR w10: 18200.36,9979 18300.36,9979 18300.36,10079 18200.36,10079 18200.36,9979
  L6_SIG2 w10: 18200.36,9869 18300.36,9869 18300.36,9969 18200.36,9969 18200.36,9869
  L7_GND3 w10: 18200.36,9759 18300.36,9759 18300.36,9859 18200.36,9859 18200.36,9759
  Bottom Layer w10: 18200.36,9649 18300.36,9649 18300.36,9749 18200.36,9749 18200.36,9649

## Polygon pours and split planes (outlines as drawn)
VCC_5V on Bottom Layer (solid, remove dead copper, pour order 248): 14725.54,5451.76 14844.96,5451.76 14844.96,5279.04 14725.54,5279.04
VDD_DDR3 on L5_PWR (solid, remove dead copper): 15194.85,8400.3 15570.85,8400.3 15570.85,7797.62 15194.85,7797.62
VCC_5V on Top Layer (solid, remove dead copper, pour order 164): 15205.08,9978.68 15295.43,9978.68 15295.43,9836.7 15205.08,9836.7
VCC_5V on L5_PWR (solid, remove dead copper): 81 vertices, not listed, extent 12745.47,5279.9 17139.78,10800.11
GND on Top Layer (solid, remove dead copper, pour order 80): 15990.29,10565.6 16382.55,10565.6 16382.55,10395.25 15990.29,10395.25
VCC_5V on Top Layer (solid, remove dead copper, pour order 82): 15984.78,10792.09 16313.53,10792.09 16313.53,10615.01 15984.78,10615.01
GND on Bottom Layer (solid, remove dead copper, pour order 250): 12826.53,5859.57 13008.64,5859.57 13008.64,5707.86 12826.53,5707.86
VCC_3V3 on Top Layer (solid, remove dead copper, pour order 84): 17451.98,10451.12 18007.13,10451.12 18007.13,10315.89 17451.98,10315.89
GND on Top Layer (solid, remove dead copper, pour order 86): 17426.17,10295.67 17606.99,10295.67 17606.99,10142.5 17426.17,10142.5
GND on Top Layer (solid, remove dead copper, pour order 88): 17882.69,10301.15 18129.26,10301.15 18129.26,10201.53 17882.69,10201.53
401_PWR on Top Layer (solid, remove dead copper, pour order 90): 17674.56,10178.7 18131.08,10178.7 18131.08,10074.09 17674.56,10074.09
GND on Bottom Layer (solid, remove dead copper, pour order 208): 17442.67,9229.84 17505.54,9229.84 17511.08,9224.31 17511.08,9154.79 17646.67,9154.79 17647.34,9155.46 17647.34,9054.67 17442.67,9054.67
401_PWR on Bottom Layer (solid, remove dead copper, pour order 210): 30 vertices, not listed, extent 17067.04,9206.27 18130.43,10180.33
$1N45009 on Top Layer (solid, remove dead copper, pour order 136): 13310.18,5775.85 13436.09,5775.85 13436.09,5375.86 13310.18,5375.86
GND on Bottom Layer (solid, remove dead copper, pour order 212): 17584.55,9860.87 17585.66,9861.98 17585.66,9998.46 17586.66,9999.46 17695.58,9999.46 17696.24,9998.79 17696.24,9822.8 17696.9,9822.13 17513.69,9822.13 17513.66,9822.16 17513.66,9859.35 17513.17,9859.84 17514.2,9860.87
GND on Bottom Layer (solid, remove dead copper, pour order 214): 17229.13,10050.49 17398.82,10050.49 17398.82,9910.02 17229.13,9910.02
401_AVDD on Bottom Layer (solid, remove dead copper, pour order 216): 17008.56,9755.18 17339.64,9755.18 17339.64,9820.48 17345.4,9826.24 17503.69,9826.24 17503.69,9862.77 17503.35,9863.1 17010.92,9863.1 17008.56,9860.74
410_PWR on Bottom Layer (solid, remove dead copper, pour order 284): 14692.48,6575.47 14692.53,6575.47 14692.53,6575.53
410_PWR on Bottom Layer (solid, remove dead copper, pour order 286): 31 vertices, not listed, extent 14619.74,5717.04 16094.62,6657
VCC_3V3 on Bottom Layer (solid, remove dead copper, pour order 288): 15876.67,6121.02 16533.33,6121.02 16604.24,6050.11 16604.24,5290.17 16605.78,5288.63 15742.56,5288.63 15737.94,5293.25 15737.94,5103.65 15727.15,5092.86 16678.23,5092.86 16693.65,5077.45 16693.65,6511.01 15881.29,6511.01 15881.29,6125.65
VCC_3V3 on Top Layer (solid, remove dead copper, pour order 174): 13360.95,9086.33 13674.26,9086.33 13674.26,8940.41 13360.95,8940.41
GND on Top Layer (solid, remove dead copper, pour order 176): 13357.86,8910.61 13560.31,8910.61 13560.31,8790.37 13357.86,8790.37
VCC_5V on Top Layer (solid, remove dead copper, pour order 138): 13061.55,5764.45 13236.83,5764.45 13236.83,5639.91 13061.55,5639.91
VCC_5V on Bottom Layer (solid, remove dead copper, pour order 256): 13065.71,5755.88 13314.29,5755.88 13314.29,5615.97 13065.71,5615.97
GND on Bottom Layer (solid, remove dead copper, pour order 218): 16923.72,10002.67 17063.86,10002.67 17063.86,9962.38 16923.72,9962.38
401_OVDD on Bottom Layer (solid, remove dead copper, pour order 220): 30 vertices, not listed, extent 16905.24,9242.26 17502.09,9807.91
GND on Bottom Layer (solid, remove dead copper, pour order 222): 17580.16,9431.72 17580.16,9430.69 17482.86,9430.69 17482.64,9430.92 17482.64,9593.08 17483.2,9593.63 17529.47,9593.63 17529.69,9593.85 17529.69,9535.85 17537.68,9527.86 17715.23,9527.86 17715.23,9431.72
GND on Bottom Layer (solid, remove dead copper, pour order 224): 16803.63,8586.59 16928.41,8586.59 16928.41,8446.87 16803.63,8446.87
GND on Bottom Layer (solid, remove dead copper, pour order 226): 17292.28,8585.84 17421.54,8585.84 17421.54,8446.12 17292.28,8446.12
VCC_3V3 on Top Layer (solid, remove dead copper, pour order 112): 16141.8,8664.34 16374.91,8664.34 16374.91,8604.56 16141.8,8604.56
GND on Bottom Layer (solid, remove dead copper, pour order 230): 17312.09,7688.19 17312.09,7775.19 17313.09,7776.19 17280.54,7776.19 17278.55,7778.18 17278.55,7817.7 17360.9,7817.7 17361.57,7818.36 17399.09,7780.84 17399.09,7777.85 17406.73,7770.21 17450.9,7770.54 17450.9,7682.87 17317.4,7682.87
7393_VDD on Bottom Layer (solid, remove dead copper, pour order 232): 17 vertices, not listed, extent 16853.95,7759.64 17141.03,8075.06
GND on Top Layer (solid, remove dead copper, pour order 118): 17313.22,7766.76 17482.58,7766.76 17482.58,7681.42 17313.22,7681.42
7393_PWR on Top Layer (solid, remove dead copper, pour order 120): 16850.79,8305.89 17317.52,8305.89 17317.52,8128.06 16850.79,8128.06
7393_PWR on Bottom Layer (solid, remove dead copper, pour order 238): 17246.93,8193.77 17432.73,8193.77 17432.73,7967.13 17246.93,7967.13
7393_PWR on Bottom Layer (solid, remove dead copper, pour order 240): 16907.82,8192.32 16986.41,8192.32 16986.41,8047.98 16907.82,8047.98
VCC_3V3 on Top Layer (solid, remove dead copper, pour order 126): 16917.95,8686.9 17125.29,8686.9 17125.29,8435.85 16917.95,8435.85
GND on Top Layer (solid, remove dead copper, pour order 128): 17147.31,8554.25 17201.11,8554.25 17201.85,8555 17201.85,8342.06 17202.6,8341.31 17420.03,8341.31 17423.76,8345.05 17423.76,8682.02 17425.26,8683.51 17142.08,8683.51 17140.59,8682.02 17147.31,8675.3
GND on Bottom Layer (solid, remove dead copper, pour order 246): 17 vertices, not listed, extent 14868.52,6564.9 15076.84,6731.73
7125_3V3 on Bottom Layer (solid, remove dead copper, pour order 258): 28 vertices, not listed, extent 13398.88,6033.83 14364.25,6492.16
GND on Bottom Layer (solid, remove dead copper, pour order 260): 13307.52,6281.78 13466.06,6281.78 13466.06,6151.6 13307.52,6151.6
GND on Bottom Layer (solid, remove dead copper, pour order 262): 13309.32,6776.24 13467.86,6776.24 13467.86,6646.06 13309.32,6646.06
VCC_3V3 on Bottom Layer (solid, remove dead copper, pour order 264): 13489.96,6852.54 13620.65,6852.54 13620.65,6534.23 13489.96,6534.23
USB_5V on Bottom Layer (solid, remove dead copper, pour order 266): 12821.01,6077.67 12900.91,6077.67 12900.91,5878.74 12821.01,5878.74
7393_VDDIO on Bottom Layer (solid, remove dead copper, pour order 268): 20 vertices, not listed, extent 16589.73,7437.21 16901.93,8162.28
7393_PWR1V8 on Bottom Layer (solid, remove dead copper, pour order 270): 29 vertices, not listed, extent 16771.98,7558.81 17637.64,8420.28
VCC_5V on Bottom Layer (solid, remove dead copper, pour order 272): 12777.57,7286.08 12923.16,7286.08 12923.16,7195.8 12777.57,7195.8
GND on L2_GND1 (solid, remove dead copper): 12073.52,11249.64 18874.95,11249.64 18874.95,4593.87 12073.52,4593.87
410_TVDD on Bottom Layer (solid, remove dead copper, pour order 276): 15307.03,6171.7 15388.79,6171.7 15389.23,6172.14 15394.48,6166.89 15394.48,6097.38 15398.85,6093.01 15521.26,6093.01 15521.26,5934.74 15517.77,5931.24 15307.91,5931.24 15307.03,5930.37
$1N104683 on Top Layer (solid, remove dead copper, pour order 0): 12882.36,10210 13252.36,10210 13252.36,10428.58 13095.78,10428.58 13091.36,10433 13091.36,10330.18 12883.53,10330.18 12882.36,10329
VCC_5V on Top Layer (solid, remove dead copper, pour order 2): 13289.36,10426 13807.26,10426 13807.26,10243 13289.36,10243
410_PVDD on Bottom Layer (solid, remove dead copper, pour order 120): 15137.51,6181.91 15137.51,6008.85 15138.36,6008 15155.36,6008 15156.36,6009 15156.36,5921 15157.36,5920 15233.36,5920 15238.36,5915 15238.36,5754.72 15078.61,5754.72 15087.32,6016 15099.04,6029.89 15099.04,6182.31 15137.11,6182.31
410_PWR on Top Layer (solid, remove dead copper, pour order 6): 15872.36,6035 16057.36,6035 16057.36,5762 15872.36,5762
GND on L5_PWR (solid, remove dead copper): 10633.33,12730.69 20232.24,12730.69 20232.24,3442.14 10633.33,3442.14
VCC_AUX on Top Layer (solid, remove dead copper, pour order 178): 13819.04,9084.4 14192.35,9084.4 14192.35,8938.48 13819.04,8938.48
GND on Top Layer (solid, remove dead copper, pour order 180): 13917.29,8909.53 14119.74,8909.53 14119.74,8789.3 13917.29,8789.3
GND on Bottom Layer (solid, remove dead copper, pour order 298): 13357.65,8909.59 13560.1,8909.59 13560.1,8789.35 13357.65,8789.35
GND on Bottom Layer (solid, remove dead copper, pour order 300): 13916.18,8911.39 14118.62,8911.39 14118.62,8791.15 13916.18,8791.15
VCC_3V3 on Bottom Layer (solid, remove dead copper, pour order 302): 13360.79,9088.91 13674.11,9088.91 13674.11,8942.99 13360.79,8942.99
FPGA_3V3 on Bottom Layer (solid, remove dead copper, pour order 304): 13816.89,9082.13 14130.21,9082.13 14130.21,8936.21 13816.89,8936.21
VCC_1V8 on Bottom Layer (solid, remove dead copper, pour order 124): 16515.36,8270 16515.36,8378 16675.36,8378 16675.36,8319 16792.36,8319 16793.36,8320 16793.36,8399 16797.36,8403 16927.36,8403 16929.36,8401 16929.36,8431 16930.36,8432 17068.87,8432 17068.87,8278.51 17060.36,8270
7393_PWR1V8 on Bottom Layer (solid, remove dead copper, pour order 126): 17272.36,8422 17529.36,8422 17529.36,8323 17272.36,8323
GND on Bottom Layer (solid, remove dead copper, pour order 128): 16968.36,9745 17373.18,9745 17373.18,9356.99 16968.36,9356.99
VCC_3V3 on L5_PWR (solid, remove dead copper): 16076.27,10127.45 16078.82,10130 16265.36,10130 16265.36,9994 16266.36,9993 16993.36,9993 17465.36,10465 18028.36,10465 18031.36,10462 18031.36,10315 18032.36,10314 17472.8,10314 17021.8,9863 16076.36,9863 16076.27,9863.09
VCC_3V3 on Bottom Layer (solid, remove dead copper, pour order 308): 16138.36,8703 17123.36,8703 17123.36,8598 16138.36,8598
VTT_DDR3 on Bottom Layer (solid, remove dead copper, pour order 130): 13418.16,8617.15 14097.36,8617.15 14097.36,8503 13418.16,8503
VTT_DDR3 on Bottom Layer (solid, remove dead copper, pour order 132): 15080.26,8610.21 15879.36,8610.21 15879.36,8508 15080.26,8508
VTT_DDR3 on Top Layer (solid, remove dead copper, pour order 18): 13418.16,8617.15 14097.36,8617.15 14097.36,8503 13418.16,8503
VCC_3V3 on L5_PWR (solid, remove dead copper): 17865.36,10462 17865.36,8790 17856.36,8781 16915.36,8781 16912.36,8778 16912.36,8561.37 17121.73,8561.37 17137.36,8577 17137.36,8704 18037.36,8704 18044.36,8711 18044.36,10462 18040.36,10466 17869.36,10466
VCC_3V3 on L5_PWR (solid, remove dead copper): 16035.68,6850.93 16035.68,6116.23 13150.44,6116.23 13150.44,6850.93 13355.54,6850.93 13355.54,9093.31 13564.79,9093.31 13564.79,6850.93
VCC_3V3 on Top Layer (solid, remove dead copper, pour order 198): 15884.36,6508 16070.85,6508 16070.85,6143.51 15884.36,6143.51
VTT_DDR3 on Top Layer (solid, remove dead copper, pour order 20): 15080.26,8610.21 15903.77,8610.21 15903.77,8508 15080.26,8508
401_DVDD on L5_PWR (solid, remove dead copper): 19 vertices, not listed, extent 16906.36,9282 17462.36,9745.82
VCC_3V3 on Bottom Layer (solid, remove dead copper, pour order 318): 16601.36,8647 16655.35,8647 16655.35,8441.74 16601.36,8441.74
FPGA_3V3 on Bottom Layer (solid, remove dead copper, pour order 320): 12565.63,8515.23 13319.36,8515.23 13319.36,8466 12565.63,8466
GND on Top Layer (solid, remove dead copper, pour order 22): 16054.36,8689 16126.36,8689 16126.36,8437 16054.36,8437
GND on Top Layer (solid, remove dead copper, pour order 24): 15076.36,8708.33 15798.75,8708.33 15798.75,8624.3 15076.36,8624.3
VEE_N5V on L5_PWR (solid, remove dead copper): 18 vertices, not listed, extent 15673.98,6510 16632.36,9683
VEE_N5V on Bottom Layer (solid, remove dead copper, pour order 324): 17077.22,6558 17077.22,6117 17004.36,6117 17004.36,6558 16536.36,6558 16536.36,6665 17079.36,6665 17079.36,6558
GND on Bottom Layer (solid, remove dead copper, pour order 142): 15076.36,8702.06 15798.75,8702.06 15798.75,8624.3 15076.36,8624.3
VCC_3V3 on Bottom Layer (solid, remove dead copper, pour order 326): 36 vertices, not listed, extent 12531.36,8938 16833.23,10137
GND on L4_GND2 (solid, remove dead copper): 11460.36,11554 19413.36,11554 19413.36,3916 11460.36,3916
GND on Top Layer (solid, remove dead copper, pour order 28): 13419.36,8732 14103.15,8732 14103.15,8623.83 13419.36,8623.83
GND on Top Layer (solid, remove dead copper, pour order 30): 13076.9,8677.91 13760.69,8677.91 13760.69,8569.74 13076.9,8569.74
GND on Bottom Layer (solid, remove dead copper, pour order 148): 13419.36,8732 14103.15,8732 14103.15,8623.83 13419.36,8623.83
GND on L7_GND3 (solid, remove dead copper): 11811.36,11519 19097.36,11519 19097.36,4495 11811.36,4495
GND on Top Layer (solid, remove dead copper, pour order 34): 15909.64,8496.01 15987.36,8496.01 15987.36,8402 15909.64,8402
GND on Top Layer (solid, remove dead copper, pour order 36): 15918.36,8675 15960.41,8675 15960.41,8542.78 15918.36,8542.78
VDD_DDR3_REF on Top Layer (solid, remove dead copper, pour order 38): 16136.36,8486 16300.74,8486 16300.74,8453.99 16136.36,8453.99
$1N87324 on Top Layer (solid, remove dead copper, pour order 40): 12927.36,9681 12987.93,9681 12987.93,9567.59 12988,9567.52 13053.03,9567.52 13053.29,9567.78 13053.29,9426.91 12942.53,9426.91 12942.53,9567.39 12941.95,9567.98 12927.37,9567.98 12927.36,9567.99
VCC_1V5 on Top Layer (solid, remove dead copper, pour order 216): 17 vertices, not listed, extent 15966.36,8541 16069.53,8770
$1N87338 on Top Layer (solid, remove dead copper, pour order 42): 12657.18,9710.6 12796.65,9710.6 12797.08,9711.04 12797.08,9563.27 12796.65,9562.83 12819.38,9562.83 12819.38,9422.93 12701.34,9422.93 12700.46,9423.8 12700.46,9628.41 12657.89,9628.41 12657.18,9629.12
VCC_5V on Top Layer (solid, remove dead copper, pour order 44): 18 vertices, not listed, extent 12892.84,9752.14 13027.89,10015.19
GND on Top Layer (solid, remove dead copper, pour order 46): 12864.8,10008.21 12960.54,10008.21 12960.54,9821.96 12864.8,9821.96
VCC_1V5 on L5_PWR (solid, remove dead copper): 14223.03,7568.67 14134.36,7480 14133.29,7481.07 14069.66,7481.07 14069.66,7566.31 14123.46,7566.31 14123.46,7613.54 14123.92,7614 14134.54,7614 14134.54,8294.53 14389.29,8294.53 14389.29,7588.6 14223.03,7588.6
$1N88386 on Top Layer (solid, remove dead copper, pour order 48): 13755.57,9673.84 13816.14,9673.84 13816.14,9560.43 13816.21,9560.37 13881.24,9560.37 13881.5,9560.63 13881.5,9419.75 13770.74,9419.75 13770.74,9560.24 13770.16,9560.82 13755.58,9560.82 13755.57,9560.84
$1N88397 on Top Layer (solid, remove dead copper, pour order 50): 13481.33,9704.7 13620.8,9704.7 13621.23,9705.14 13621.23,9557.36 13620.8,9556.92 13643.53,9556.92 13643.53,9417.02 13525.49,9417.02 13524.61,9417.89 13524.61,9622.5 13482.04,9622.5 13481.33,9623.22
VCC_5V on Top Layer (solid, remove dead copper, pour order 52): 18 vertices, not listed, extent 13718.92,9743.11 13853.97,10006.16
GND on Top Layer (solid, remove dead copper, pour order 54): 13688.62,9994.54 13784.37,9994.54 13784.37,9808.29 13688.62,9808.29
VDD_DDR3 on Bottom Layer (solid, remove dead copper, pour order 336): 15686.73,8097.14 15878.22,8097.14 15884.36,8091 15884.36,8344 15877.36,8351 15687.36,8351 15683.36,8347 15683.36,8100.52
GND on Bottom Layer (solid, remove dead copper, pour order 338): 15903.36,8339 15903.36,7839 15904.36,7838 15904.36,7713 15898.36,7707 15977.36,7707 15980.36,7704 15980.36,8183 15982.36,8185 16177.36,8185 16180.36,8182 16180.36,8338 16178.36,8340 15904.36,8340
VCC_1V5 on Bottom Layer (solid, remove dead copper, pour order 340): 13845.36,7556 14140.81,7556 14140.81,7488.46 14136.36,7484 14069.36,7484 14064.36,7479 13961.36,7479 13926.36,7444 13846.36,7444 13844.36,7442 13844.36,7555
VCC_1V5 on Bottom Layer (solid, remove dead copper, pour order 342): 24 vertices, not listed, extent 15143.36,7404 16152.88,8162
GND on Top Layer (solid, remove dead copper, pour order 56): 26 vertices, not listed, extent 15350.47,9532.89 15668.41,9925.74
$1N89126 on Top Layer (solid, remove dead copper, pour order 58): 14588.14,9663.96 14588.14,9554.59 14586.49,9552.94 14560.71,9552.94 14560.01,9552.24 14560.01,9407.66 14559.31,9406.95 14666.86,9406.95 14667.57,9407.66 14667.57,9553.18 14622.58,9553.18 14620.09,9550.69 14620.09,9663.96
VCC_1V2 on Top Layer (solid, remove dead copper, pour order 60): 14846.91,9784.57 15117.91,9784.57 15117.91,9696.52 14846.91,9696.52
$1N93752 on Top Layer (solid, remove dead copper, pour order 62): 14790.11,9414.62 14970.24,9414.15 14970.94,9691.48 14838.62,9691.95 14837.91,9691.25 14837.91,9708.47 14836.51,9709.87 14711.02,9709.87 14708.91,9707.77 14708.91,9614.97 14789.41,9614.97 14789.76,9614.62 14789.76,9414.97
$1N93752 on Top Layer (solid, remove dead copper, pour order 64): 14904.71,9415.02 14959.17,9415.21 14904.7,9414.97
VCC_5V on Top Layer (solid, remove dead copper, pour order 66): 14547.72,9764.83 14600.6,9764.83 14600.6,9809.54 14590.61,9809.47 14589.55,9810.52 14589.55,9975.8 14519.96,9975.8 14519.96,9844.85 14519.63,9844.53 14547.24,9844.53 14547.72,9844.04
GND on Top Layer (solid, remove dead copper, pour order 68): 14640.14,9742.2 14640.84,9742.9 14640.84,9857.96 14640.14,9858.66 14641.55,9860.07 14671.77,9860.07 14671.77,9975.83 14673.42,9977.47 14606.86,9977.47 14606.16,9976.77 14606.16,9847.1 14605.22,9846.17 14605.22,9743.06 14604.91,9742.75 14605.46,9742.2
GND on Top Layer (solid, remove dead copper, pour order 70): 22 vertices, not listed, extent 14608.16,9699.61 15117.89,9910.86
GND on Top Layer (solid, remove dead copper, pour order 72): 13363.44,10216.8 13806.86,10216.8 13806.86,10072.33 13363.44,10072.33
GND on Bottom Layer (solid, remove dead copper, pour order 344): 14062.69,7596 14065.13,7593.56 14065.13,7678.14 14058.86,7684.41 14038.86,7684.41 14038.86,7784.91 14034.94,7781 13999.36,7781 13999.36,7719.49 13988.34,7708.47 13765.83,7708.47 13760.36,7703 13760.36,7599 13763.36,7596
VCC_1V2 on Bottom Layer (solid, remove dead copper, pour order 346): 14983.36,8554 14983.36,8610 14976.36,8617 14895.36,8617 14895.36,8702.55 14898.09,8705.29 15049.65,8705.29 15050.36,8706 15050.36,8549.37 15050.91,8548.82 14988.53,8548.82
VCC_1V2 on L5_PWR (solid, remove dead copper): 32 vertices, not listed, extent 14470.3,7748.24 15117.36,9785
VCC_3V3 on Top Layer (solid, remove dead copper, pour order 74): 12528.27,9702.62 12636.47,9702.62 12636.47,9539.98 12528.27,9539.98
VCC_1V5 on Top Layer (solid, remove dead copper, pour order 76): 13363.73,9704.87 13471.93,9704.87 13471.93,9542.23 13363.73,9542.23
VEE_N5V on Top Layer (solid, remove dead copper, pour order 78): 15673.98,9676.31 15783.72,9676.31 15783.72,9615.54 15673.98,9615.54
FPGA_3V3 on Bottom Layer (solid, remove dead copper, pour order 350): 14535.36,8652 14602.36,8652 14602.36,8340.35 14535.36,8340.35
GND on Bottom Layer (solid, remove dead copper, pour order 352): 14612.66,8577.72 14675.36,8577.72 14675.36,8341 14612.66,8341
FPGA_3V3 on L6_SIG2 (solid, remove dead copper): 25 vertices, not listed, extent 14390.79,7755 14765.36,8455
FPGA_3V3 on L5_PWR (solid, remove dead copper): 14218.36,7459 15044.6,7459 15048.8,7463.2 15048.8,7562.56 15048.36,7563 14812.36,7563 14811.36,7564 14811.36,7733.56 14424.93,7733.56 14423.36,7731.99 14423.36,7571.27 14243.34,7571.27 14240.08,7574.53 14240.08,7480.72
VCC_1V5 on L5_PWR (solid, remove dead copper): 18 vertices, not listed, extent 13361.36,7368 13940.44,9704.87
FPGA_3V3 on L5_PWR (solid, remove dead copper): 27 vertices, not listed, extent 13914.45,7174 14609.36,9082.13
FPGA_3V3 on Bottom Layer (solid, remove dead copper, pour order 362): 13952.36,7328 14263.36,7328 14264.36,7327 14264.36,7396.5 14266.36,7398.5 14394.98,7398.5 14397.67,7395.81 14397.67,7457.16 14410.52,7470.01 14452.35,7470.01 14454.36,7468 14454.36,7265.73 14449.89,7261.26 13951.36,7261.26 13951.36,7327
